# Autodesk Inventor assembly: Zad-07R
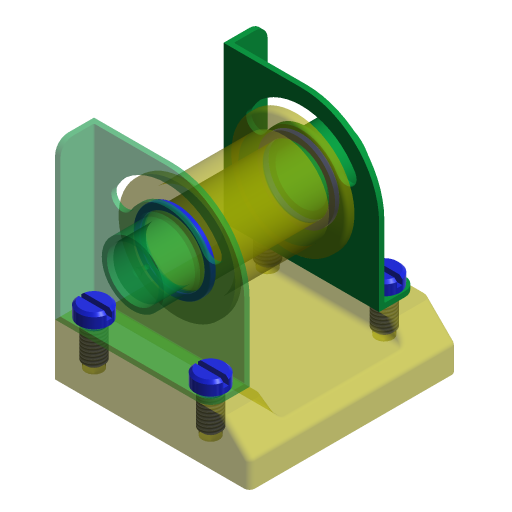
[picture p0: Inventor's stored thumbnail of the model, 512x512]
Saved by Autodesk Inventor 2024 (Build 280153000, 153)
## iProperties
Created: 2023-03
Part Number: Zad-07R
Document SubType Name: Assembly
Designer: Andrzej Jaskulski
Checked By: A.J.
Engr Approved By: Andrzej Jaskulski
Mfg Approved By: Andrzej Jaskulski
Authority: A.J.
Company: ATC
Control State: 0
Master: False
Checked Out: False
Shininess: 20.0
Length Units: 11269
Angle Units: 11279
Time Units: 11290
Mass Units: 11283
Length Display Precision: 3
Angle Display Precision: 2
Density: 0.0
Volumn: 0.0
Area: 0.0
PropertySet Name: Model Information
Title: A.J.: Kurs R2024-MEP
Author: Andrzej Jaskulski
Revision Number: 1/24
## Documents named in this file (6)
- C:\Users\AndJas\Documents\R2024-MEP\Obszar roboczy\Zad-07R.iam
- C:\Users\AndJas\Documents\R2024-MEP\Obszar roboczy\PZESP1.iam
- C:\Users\AndJas\Documents\R2024-MEP\Obszar roboczy\WP7.ipt
- C:\Users\AndJas\Documents\R2024-MEP\Obszar roboczy\P7.ipt
- C:\Users\AndJas\Documents\R2024-MEP\Obszar roboczy\WL7.ipt
- C:\Users\AndJas\Documents\R2024-MEP\Obszar roboczy\W7.ipt
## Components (8 placed, 5 different names)
1. P7:1 — Zestawiające:1, Zestawiające:2, Zestawiające:3, Zestawiające:4, Zestawiające:5, Zestawiające:6
2. WP7:1 — Zestawiające:1, Zestawiające:3, Zestawiające:4, Wstawiające:1, Wstawiające:2, Wstawiające:3
3. WL7:1 — Zestawiające:2, Zestawiające:5, Zestawiające:6, Wstawiające:4, Wstawiające:5
4. PZESP1:1 [sub-assembly] — Wstawiające:1
5. W7:1 — Wstawiające:2
6. W7:2 — Wstawiające:3
7. W7:3 — Wstawiające:5
8. W7:4 — Wstawiające:4
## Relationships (11: Mate 6, Insert 5)
- Zestawiające:1 [Mate]: P7:1 ↔ WP7:1
- Zestawiające:2 [Mate]: P7:1 ↔ WL7:1
- Zestawiające:3 [Mate]: P7:1 ↔ WP7:1
- Zestawiające:4 [Mate]: P7:1 ↔ WP7:1
- Zestawiające:5 [Mate]: P7:1 ↔ WL7:1
- Zestawiające:6 [Mate]: P7:1 ↔ WL7:1
- Wstawiające:1 [Insert]: WP7:1 ↔ PZESP1:1
- Wstawiające:2 [Insert]: WP7:1 ↔ W7:1
- Wstawiające:3 [Insert]: WP7:1 ↔ W7:2
- Wstawiające:4 [Insert]: WL7:1 ↔ W7:4
- Wstawiające:5 [Insert]: WL7:1 ↔ W7:3
